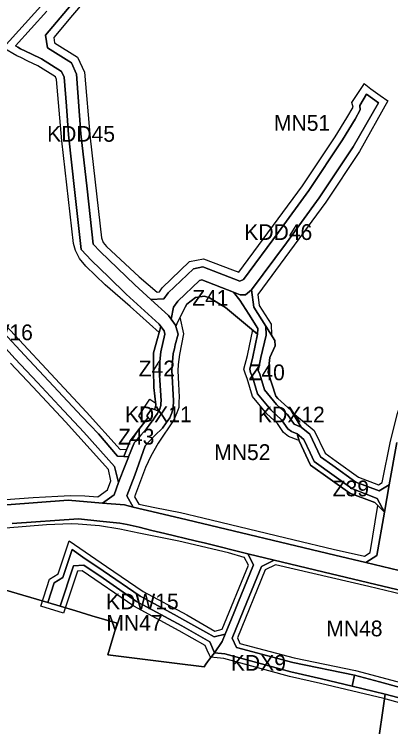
# Model space of a CAD drawing. Extents: x 7428841 to 7433518, y 5545054 to 5546840.
# Drawn here: x 7432461.8 to 7432700.7, y 5545406.8 to 5545858.6 of the extents above; entities that cross this region are included whole.
import ezdxf

# ---------------------------------------------------------------- set-up
doc = ezdxf.new("R2010")
doc.units = 0
for name, color, linetype in [('linie_rozgraniczajace', 7, 'Continuous'), ('linie_zabudowy_nieprzekraczalne', 7, 'Continuous'), ('oznaczenia_przeznaczen', 7, 'Continuous')]:
    doc.layers.add(name, color=color, linetype=linetype)

msp = doc.modelspace()

# ---------------------------------------------------------------- linework, layer by layer
at = {"layer": 'linie_rozgraniczajace'}
for points in [[(7432558.63, 5545936.52), (7432481.55, 5545845.41), (7432482.91, 5545837.42), (7432498.02, 5545827.85), (7432501.36, 5545820.69), (7432504.13, 5545782.79), (7432507.98, 5545747.86), (7432511.82, 5545712.93), (7432516.4, 5545708.16), (7432527.38, 5545697.61), (7432538.36, 5545687.05), (7432548.47, 5545677.77), (7432559.57, 5545667.58), (7432561.31, 5545665.33), (7432564.13, 5545661.41), (7432564.37, 5545660.57), (7432565.72, 5545655.83), (7432563.88, 5545649), (7432563.37, 5545646.48), (7432562.64, 5545643.49), (7432561.84, 5545633.01), (7432562.94, 5545613.42), (7432562.66, 5545609.09), (7432561.75, 5545605.81), (7432560.45, 5545602.74), (7432558.2, 5545599.48), (7432555.94, 5545596.21), (7432550.99, 5545591.47), (7432544.82, 5545584.91), (7432538.38, 5545566.31), (7432533.23, 5545553.18), (7432537.26, 5545546.04), (7432531.75, 5545547.42), (7432517.74, 5545548.62), (7432525.1, 5545553.96), (7432528.01, 5545561.6), (7432530.93, 5545569.23), (7432534.29, 5545577.67), (7432534.38, 5545577.92), (7432537.64, 5545586.11), (7432538.15, 5545587.09), (7432538.76, 5545587.71), (7432542.1, 5545591.65), (7432545.44, 5545595.6), (7432547.39, 5545598), (7432549.14, 5545600.46), (7432549.46, 5545600.9), (7432551.52, 5545603.81), (7432552.57, 5545605.24), (7432553.4, 5545606.61), (7432553.55, 5545606.89), (7432554.01, 5545607.81), (7432554.18, 5545608.45), (7432554.73, 5545610.42), (7432554.82, 5545612.03), (7432554.93, 5545613.48), (7432553.83, 5545633.1), (7432554.4, 5545640.6), (7432554.84, 5545644.48), (7432557.42, 5545655.77), (7432556.82, 5545657.87), (7432554.78, 5545660.7), (7432553.66, 5545662.15), (7432532.88, 5545681.22), (7432521.81, 5545691.86), (7432510.74, 5545702.51), (7432504.17, 5545709.36), (7432500.16, 5545745.7), (7432496.16, 5545782.06), (7432494.83, 5545800.35), (7432493.49, 5545818.64), (7432491.76, 5545822.34), (7432479.05, 5545830.4), (7432472.53, 5545833.46), (7432465.78, 5545836.73), (7432464.01, 5545837.83), (7432462.66, 5545838.66), (7432482.47, 5545860.49)], [(7432704.49, 5545587.01), (7432699.79, 5545560.16), (7432693.37, 5545556.39), (7432678.63, 5545561.96), (7432664.03, 5545572.38), (7432656.21, 5545578.01), (7432649.37, 5545592.44), (7432643.95, 5545596.86), (7432637.44, 5545607.32), (7432629.14, 5545614.87), (7432627.79, 5545616.47), (7432623.02, 5545631.54), (7432623.91, 5545641.02), (7432627.37, 5545648.45), (7432627.24, 5545651.74), (7432621.37, 5545660.86), (7432613.72, 5545672.85), (7432612.39, 5545683.92), (7432634.53, 5545713.76), (7432655.33, 5545742.28), (7432676.79, 5545774.6), (7432693.03, 5545802.53), (7432685.42, 5545807.95), (7432681.02, 5545800.86), (7432681.32, 5545798.03), (7432678.08, 5545792.12), (7432670.04, 5545778.9), (7432648.77, 5545746.86), (7432629.53, 5545720.49), (7432607.23, 5545690.4), (7432604.93, 5545689.4), (7432581.47, 5545698.44), (7432575.45, 5545697.23), (7432559.5, 5545681.95), (7432556.79, 5545678.11), (7432548.47, 5545677.77), (7432538.36, 5545687.05), (7432527.38, 5545697.61), (7432516.4, 5545708.16), (7432511.82, 5545712.93), (7432507.98, 5545747.86), (7432504.13, 5545782.79), (7432501.36, 5545820.69), (7432498.02, 5545827.85), (7432482.91, 5545837.42), (7432481.55, 5545845.41), (7432558.63, 5545936.52)], [(7432482.47, 5545860.49), (7432462.66, 5545838.66), (7432464.01, 5545837.83), (7432465.78, 5545836.73), (7432472.53, 5545833.46), (7432479.05, 5545830.4), (7432491.76, 5545822.34), (7432493.49, 5545818.64), (7432494.83, 5545800.35), (7432496.16, 5545782.06), (7432500.16, 5545745.7), (7432504.17, 5545709.36), (7432510.74, 5545702.51), (7432521.81, 5545691.86), (7432532.88, 5545681.22), (7432553.66, 5545662.15), (7432554.78, 5545660.7), (7432552.65, 5545653.05), (7432550.12, 5545643.98), (7432550.23, 5545632.91), (7432550.34, 5545621.85), (7432551.64, 5545610.97), (7432551.31, 5545609.63), (7432550.74, 5545608.07), (7432549.17, 5545608.7), (7432545.96, 5545604.05), (7432546.83, 5545602.92), (7432542.34, 5545597.27), (7432535.29, 5545588.16), (7432531.26, 5545578.11)], [(7432454.85, 5545656.77), (7432468.21, 5545642.48), (7432486.68, 5545622.85), (7432504.73, 5545603.59), (7432515.22, 5545592.47), (7432527.36, 5545578.35), (7432531.26, 5545578.11), (7432534.38, 5545577.92), (7432534.29, 5545577.67), (7432530.93, 5545569.23), (7432528.01, 5545561.6), (7432525.32, 5545571.85), (7432505.87, 5545593.58), (7432490.18, 5545610.4), (7432476.54, 5545625.02), (7432462.29, 5545640.03), (7432450.07, 5545653.35)], [(7432531.26, 5545578.11), (7432527.36, 5545578.35), (7432515.22, 5545592.47), (7432504.73, 5545603.59), (7432486.68, 5545622.85), (7432468.21, 5545642.48), (7432454.85, 5545656.77)], [(7432450.07, 5545653.35), (7432462.29, 5545640.03), (7432476.54, 5545625.02), (7432490.18, 5545610.4), (7432505.87, 5545593.58), (7432525.32, 5545571.85), (7432528.01, 5545561.6), (7432525.1, 5545553.96), (7432517.74, 5545548.62), (7432495.96, 5545550.47), (7432457.17, 5545547.49)], [(7432706.04, 5545505.84), (7432684.8, 5545510.91), (7432691.96, 5545515.49), (7432696.77, 5545542.91), (7432699.79, 5545560.16), (7432704.49, 5545587.01)], [(7432457.17, 5545547.49), (7432495.96, 5545550.47), (7432517.74, 5545548.62), (7432531.75, 5545547.42), (7432537.26, 5545546.04), (7432552.76, 5545542.38), (7432571.55, 5545537.93), (7432665.2, 5545515.59), (7432684.8, 5545510.91), (7432706.04, 5545505.84)], [(7432460.41, 5545535.59), (7432502.51, 5545538.7), (7432516.17, 5545537.12), (7432528.77, 5545535.81), (7432533.47, 5545535.03), (7432540.95, 5545533.32), (7432549.12, 5545531.31), (7432557.29, 5545529.31), (7432576.6, 5545524.79), (7432583.18, 5545523.21), (7432610.05, 5545516.41), (7432613.65, 5545509.47), (7432603.7, 5545485.19), (7432601.07, 5545478.78), (7432595.66, 5545465.56), (7432588.62, 5545463.74), (7432583.36, 5545466.72), (7432570.05, 5545474.18), (7432563.25, 5545477.9), (7432548.07, 5545486.13), (7432541.74, 5545489.52), (7432518.29, 5545505.58), (7432505.37, 5545514.4), (7432498.47, 5545519.11), (7432492.64, 5545501.43), (7432487.11, 5545498.13), (7432483.05, 5545485.51), (7432456.34, 5545493.47)], [(7432747.03, 5545483.73), (7432662.85, 5545503.81), (7432626.69, 5545512.44), (7432610.05, 5545516.41), (7432583.18, 5545523.21), (7432576.6, 5545524.79), (7432557.29, 5545529.31), (7432549.12, 5545531.31), (7432540.95, 5545533.32), (7432533.47, 5545535.03), (7432528.77, 5545535.81), (7432516.17, 5545537.12), (7432502.51, 5545538.7), (7432460.41, 5545535.59)], [(7432456.34, 5545493.47), (7432483.05, 5545485.51), (7432490.84, 5545483.2), (7432500.9, 5545480.2), (7432510.96, 5545477.21), (7432527.03, 5545472.42), (7432521.06, 5545452.31), (7432563.57, 5545447.17), (7432582.27, 5545444.83), (7432583.41, 5545446.45), (7432584.43, 5545447.9), (7432585.75, 5545449.6), (7432588.89, 5545453.57), (7432595.36, 5545452.95), (7432616.31, 5545447.31), (7432637.26, 5545441.66), (7432656.79, 5545437.08), (7432676.32, 5545432.5), (7432697.15, 5545427.52), (7432691.97, 5545390.71)], [(7432691.97, 5545390.71), (7432697.15, 5545427.52), (7432716.32, 5545422.39), (7432739.46, 5545413.31), (7432747.98, 5545444.14), (7432756.49, 5545474.97), (7432764.84, 5545479.48), (7432780.35, 5545475.78), (7432795.86, 5545472.08), (7432847.64, 5545461.54), (7432848.64, 5545458.32), (7432833.76, 5545435.16), (7432818.19, 5545411.13), (7432812.33, 5545402.01)]]:
    msp.add_lwpolyline(points, dxfattribs=at)
for points in [[(7432548.47, 5545677.77), (7432556.79, 5545678.11), (7432559.5, 5545681.95), (7432575.45, 5545697.23), (7432581.47, 5545698.44), (7432604.93, 5545689.4), (7432607.23, 5545690.4), (7432629.53, 5545720.49), (7432648.77, 5545746.86), (7432670.04, 5545778.9), (7432678.08, 5545792.12), (7432681.32, 5545798.03), (7432681.02, 5545800.86), (7432685.42, 5545807.95), (7432693.03, 5545802.53), (7432676.79, 5545774.6), (7432655.33, 5545742.28), (7432634.53, 5545713.76), (7432612.39, 5545683.92), (7432608.61, 5545680.68), (7432605.11, 5545680.76), (7432601, 5545682.34), (7432580.76, 5545690.14), (7432579.31, 5545689.85), (7432565.61, 5545676.72), (7432562.9, 5545672.94), (7432561.31, 5545665.33), (7432559.57, 5545667.58)], [(7432561.31, 5545665.33), (7432562.9, 5545672.94), (7432565.61, 5545676.72), (7432579.31, 5545689.85), (7432580.76, 5545690.14), (7432601, 5545682.34), (7432604.89, 5545677.39), (7432610.64, 5545668.37), (7432616.4, 5545659.34), (7432616.25, 5545655.79), (7432606.08, 5545664.16), (7432595.85, 5545672.58), (7432585.65, 5545678.8), (7432582.41, 5545679.94), (7432576.7, 5545679), (7432571.34, 5545674.86), (7432570.19, 5545672.88), (7432565.01, 5545662.38), (7432564.37, 5545660.57), (7432564.13, 5545661.41)], [(7432601, 5545682.34), (7432605.11, 5545680.76), (7432608.61, 5545680.68), (7432612.39, 5545683.92), (7432613.72, 5545672.85), (7432621.37, 5545660.86), (7432621.6, 5545655.03), (7432618.17, 5545640.87), (7432616.66, 5545632.77), (7432617.6, 5545630.44), (7432620.68, 5545620.39), (7432628.31, 5545611.19), (7432635.29, 5545604.75), (7432639.46, 5545598.62), (7432643.95, 5545596.86), (7432649.37, 5545592.44), (7432656.21, 5545578.01), (7432664.03, 5545572.38), (7432678.63, 5545561.96), (7432693.37, 5545556.39), (7432699.79, 5545560.16), (7432696.77, 5545542.91), (7432692.18, 5545551.45), (7432676.08, 5545557.93), (7432652.04, 5545575.08), (7432649.54, 5545580.41), (7432645.57, 5545588.88), (7432641.39, 5545592.49), (7432637.64, 5545593.96), (7432635.33, 5545595.81), (7432631.48, 5545601.46), (7432624.67, 5545607.74), (7432620.43, 5545612.85), (7432616.19, 5545617.97), (7432612.88, 5545628.77), (7432611.8, 5545631.44), (7432611.2, 5545633.59), (7432613.13, 5545641.46), (7432616.25, 5545655.79), (7432616.4, 5545659.34), (7432610.64, 5545668.37), (7432604.89, 5545677.39)], [(7432533.23, 5545553.18), (7432538.38, 5545566.31), (7432544.82, 5545584.91), (7432550.99, 5545591.47), (7432555.94, 5545596.21), (7432558.2, 5545599.48), (7432560.45, 5545602.74), (7432561.75, 5545605.81), (7432562.66, 5545609.09), (7432562.94, 5545613.42), (7432561.84, 5545633.01), (7432562.64, 5545643.49), (7432563.37, 5545646.48), (7432563.88, 5545649), (7432565.72, 5545655.83), (7432564.37, 5545660.57), (7432565.01, 5545662.38), (7432570.19, 5545672.88), (7432571.34, 5545674.86), (7432576.7, 5545679), (7432582.41, 5545679.94), (7432585.65, 5545678.8), (7432595.85, 5545672.58), (7432606.08, 5545664.16), (7432616.25, 5545655.79), (7432613.13, 5545641.46), (7432611.2, 5545633.59), (7432611.8, 5545631.44), (7432612.88, 5545628.77), (7432616.19, 5545617.97), (7432620.43, 5545612.85), (7432624.67, 5545607.74), (7432631.48, 5545601.46), (7432635.33, 5545595.81), (7432637.64, 5545593.96), (7432641.39, 5545592.49), (7432642.57, 5545588.03), (7432649.87, 5545572.71), (7432674.82, 5545554.85), (7432690.54, 5545548.91), (7432696.77, 5545542.91), (7432691.96, 5545515.49), (7432684.8, 5545510.91), (7432665.2, 5545515.59), (7432571.55, 5545537.93), (7432552.76, 5545542.38), (7432537.26, 5545546.04)], [(7432550.74, 5545608.07), (7432551.31, 5545609.63), (7432551.64, 5545610.97), (7432550.34, 5545621.85), (7432550.23, 5545632.91), (7432550.12, 5545643.98), (7432552.65, 5545653.05), (7432554.78, 5545660.7), (7432556.82, 5545657.87), (7432557.42, 5545655.77), (7432554.84, 5545644.48), (7432554.4, 5545640.6), (7432553.83, 5545633.1), (7432554.93, 5545613.48), (7432554.82, 5545612.03), (7432554.73, 5545610.42), (7432554.18, 5545608.45), (7432554.01, 5545607.81), (7432553.55, 5545606.89), (7432550.76, 5545608.06)], [(7432616.66, 5545632.77), (7432618.17, 5545640.87), (7432621.6, 5545655.03), (7432621.37, 5545660.86), (7432627.24, 5545651.74), (7432627.37, 5545648.45), (7432623.91, 5545641.02), (7432623.02, 5545631.54), (7432627.79, 5545616.47), (7432629.14, 5545614.87), (7432637.44, 5545607.32), (7432643.95, 5545596.86), (7432639.46, 5545598.62), (7432635.29, 5545604.75), (7432628.31, 5545611.19), (7432620.68, 5545620.39), (7432617.6, 5545630.44)], [(7432545.96, 5545604.05), (7432549.17, 5545608.7), (7432550.74, 5545608.07), (7432550.76, 5545608.06), (7432553.55, 5545606.89), (7432553.4, 5545606.61), (7432552.57, 5545605.24), (7432551.52, 5545603.81), (7432549.46, 5545600.9), (7432549.14, 5545600.46), (7432546.83, 5545602.92)], [(7432531.26, 5545578.11), (7432535.29, 5545588.16), (7432542.34, 5545597.27), (7432546.83, 5545602.92), (7432549.14, 5545600.46), (7432547.39, 5545598), (7432545.44, 5545595.6), (7432542.1, 5545591.65), (7432538.76, 5545587.71), (7432538.15, 5545587.09), (7432537.64, 5545586.11), (7432534.38, 5545577.92)], [(7432641.39, 5545592.49), (7432645.57, 5545588.88), (7432649.54, 5545580.41), (7432652.04, 5545575.08), (7432676.08, 5545557.93), (7432692.18, 5545551.45), (7432696.77, 5545542.91), (7432690.54, 5545548.91), (7432674.82, 5545554.85), (7432649.87, 5545572.71), (7432642.57, 5545588.03)], [(7432483.05, 5545485.51), (7432487.11, 5545498.13), (7432492.64, 5545501.43), (7432498.47, 5545519.11), (7432505.37, 5545514.4), (7432518.29, 5545505.58), (7432541.74, 5545489.52), (7432548.07, 5545486.13), (7432563.25, 5545477.9), (7432570.05, 5545474.18), (7432583.36, 5545466.72), (7432588.62, 5545463.74), (7432595.66, 5545465.56), (7432593.73, 5545460.86), (7432588.89, 5545453.57), (7432585.81, 5545460.72), (7432576.95, 5545465.71), (7432568.09, 5545470.7), (7432546.59, 5545482.37), (7432539.42, 5545486.26), (7432518.13, 5545501.07), (7432505.88, 5545509.21), (7432499.27, 5545508.77), (7432490.84, 5545483.2)], [(7432588.89, 5545453.57), (7432593.73, 5545460.86), (7432595.66, 5545465.56), (7432601.07, 5545478.78), (7432603.7, 5545485.19), (7432613.65, 5545509.47), (7432610.05, 5545516.41), (7432626.69, 5545512.44), (7432618.66, 5545508.52), (7432609.36, 5545485.76), (7432600.07, 5545462.99), (7432602.92, 5545457.15), (7432638.64, 5545447.5), (7432677.64, 5545439.51), (7432676.32, 5545432.5), (7432656.79, 5545437.08), (7432637.26, 5545441.66), (7432616.31, 5545447.31), (7432595.36, 5545452.95)], [(7432490.84, 5545483.2), (7432499.27, 5545508.77), (7432505.88, 5545509.21), (7432518.13, 5545501.07), (7432539.42, 5545486.26), (7432546.59, 5545482.37), (7432568.09, 5545470.7), (7432576.95, 5545465.71), (7432585.81, 5545460.72), (7432588.89, 5545453.57), (7432585.75, 5545449.6), (7432584.43, 5545447.9), (7432583.41, 5545446.45), (7432582.27, 5545444.83), (7432563.57, 5545447.17), (7432521.06, 5545452.31), (7432527.03, 5545472.42), (7432510.96, 5545477.21), (7432500.9, 5545480.2)], [(7432600.07, 5545462.99), (7432609.36, 5545485.76), (7432618.66, 5545508.52), (7432626.69, 5545512.44), (7432662.85, 5545503.81), (7432747.03, 5545483.73), (7432751.3, 5545476.36), (7432750.98, 5545475.2), (7432737.03, 5545425.73), (7432731, 5545422.9), (7432721.44, 5545426.38), (7432706.79, 5545431.71), (7432693.5, 5545435.26), (7432677.64, 5545439.51), (7432638.64, 5545447.5), (7432602.92, 5545457.15)], [(7432676.32, 5545432.5), (7432677.64, 5545439.51), (7432693.5, 5545435.26), (7432706.79, 5545431.71), (7432721.44, 5545426.38), (7432731, 5545422.9), (7432737.03, 5545425.73), (7432750.98, 5545475.2), (7432751.3, 5545476.36), (7432747.03, 5545483.73), (7432764.84, 5545479.48), (7432756.49, 5545474.97), (7432747.98, 5545444.14), (7432739.46, 5545413.31), (7432716.32, 5545422.39), (7432697.15, 5545427.52)]]:
    msp.add_lwpolyline(points, close=True, dxfattribs=at)
at = {"layer": 'linie_zabudowy_nieprzekraczalne'}
for points in [[(7432553.71, 5545656.87), (7432535.29, 5545673.24), (7432519.45, 5545687.14), (7432507.2, 5545698.97), (7432503.13, 5545703.79), (7432500.72, 5545708.71), (7432499.42, 5545713.29), (7432491.95, 5545778.42), (7432488.57, 5545817.36), (7432487.85, 5545818.9), (7432476.64, 5545826.01), (7432470.39, 5545828.94), (7432465.86, 5545831.11), (7432463.4, 5545832.33), (7432454.78, 5545837.43), (7432478.74, 5545863.82), (7432512.66, 5545902.33), (7432533.86, 5545927.37), (7432576.75, 5545979.38), (7432604.6, 5546013.61), (7432608.93, 5546021.42)], [(7432618.1, 5546001.67), (7432562.48, 5545933.32), (7432525.76, 5545889.94), (7432498.81, 5545858.08), (7432486.83, 5545843.91), (7432487.35, 5545840.44), (7432501.92, 5545831.32), (7432506.28, 5545821.97), (7432509.87, 5545780.1), (7432517.13, 5545716.81), (7432518.21, 5545713.86), (7432520.26, 5545711.39), (7432541.01, 5545692.16), (7432552.5, 5545682.35)], [(7432695.36, 5545561.62), (7432700.58, 5545587.88), (7432704.91, 5545605.53), (7432707.27, 5545612.64), (7432721.28, 5545651), (7432735.53, 5545683.2), (7432746.17, 5545705.98), (7432757.15, 5545728.45), (7432775.79, 5545760.35), (7432791.15, 5545790.68), (7432794.62, 5545804.39), (7432795.08, 5545814.24), (7432795.4, 5545826.14), (7432797.74, 5545849.15), (7432799.24, 5545860.38)], [(7432683.89, 5545814.67), (7432687.98, 5545811.34), (7432693.96, 5545807.08), (7432698.83, 5545803.75), (7432680.93, 5545771.53), (7432659.43, 5545739.41), (7432616.28, 5545680.91)], [(7432672.76, 5545792.96), (7432676.96, 5545799.8), (7432676.08, 5545802.71), (7432684.01, 5545814.64)], [(7432552.5, 5545682.35), (7432553.97, 5545682.51), (7432555.69, 5545685.22), (7432573.04, 5545701.85), (7432581.91, 5545703.63), (7432600.21, 5545696.54), (7432604.38, 5545694.97), (7432644.68, 5545749.73), (7432665.35, 5545780.9), (7432672.76, 5545792.96)], [(7432616.28, 5545680.91), (7432617.18, 5545674.02), (7432624.84, 5545662.01), (7432625.09, 5545655.42)], [(7432444.52, 5545673.75), (7432484.92, 5545630.57), (7432507.68, 5545606.3), (7432528.91, 5545582.62), (7432533.15, 5545582.8)], [(7432566.82, 5545666.54), (7432569.21, 5545656.07), (7432566.61, 5545642.85), (7432565.87, 5545636.57), (7432565.58, 5545632.44), (7432565.97, 5545624.16), (7432566.37, 5545615.87), (7432566.3, 5545612.9), (7432566.2, 5545609.3), (7432564.94, 5545605.82), (7432563.04, 5545601.52), (7432553.21, 5545586.6), (7432548.38, 5545578.46), (7432545.07, 5545571.13), (7432538.14, 5545552.62), (7432540.74, 5545548.01)], [(7432641.94, 5545588.52), (7432635.87, 5545590.89), (7432632.73, 5545593.4), (7432628.81, 5545599.16), (7432622.13, 5545605.33), (7432613.05, 5545616.27), (7432609.58, 5545627.59), (7432608.48, 5545630.31), (7432607.57, 5545633.57), (7432609.73, 5545642.25), (7432613.25, 5545658.43)], [(7432523.11, 5545562.82), (7432521.67, 5545569.83), (7432509.92, 5545582.91), (7432494.2, 5545600.12), (7432473.62, 5545622.28), (7432459.36, 5545637.3)], [(7432544.08, 5545599.56), (7432540.91, 5545604.01), (7432547.85, 5545614.48), (7432551.58, 5545612.01)], [(7432638.48, 5545605.85), (7432652.19, 5545594.65), (7432658.99, 5545580.32), (7432666.07, 5545575.22), (7432680.29, 5545565.08), (7432693.04, 5545560.26), (7432695.36, 5545561.62)], [(7432247.77, 5545573.92), (7432259.56, 5545571.46), (7432280.88, 5545567.35), (7432316.46, 5545560.32), (7432327.27, 5545558.29), (7432357.63, 5545553.16), (7432378.33, 5545550.62), (7432387.21, 5545550.01), (7432404.47, 5545548.7), (7432419.02, 5545548.35), (7432424.04, 5545548.71), (7432447.45, 5545550.3), (7432473.79, 5545552.27), (7432489.45, 5545553.01), (7432497.43, 5545553.34), (7432506.55, 5545553.25), (7432514.8, 5545552.66)], [(7432514.8, 5545552.66), (7432520.96, 5545557.14), (7432523.11, 5545562.82)], [(7432540.83, 5545547.97), (7432550.9, 5545545.9), (7432567.2, 5545542.56), (7432581.53, 5545539.29), (7432639.46, 5545525.38), (7432664.09, 5545519.42), (7432684.01, 5545515.04)], [(7432684.01, 5545515.04), (7432687.56, 5545517.33), (7432692.58, 5545547.04)], [(7432607.74, 5545514.22), (7432597.67, 5545516.99), (7432566.17, 5545524.4), (7432540.88, 5545529.57), (7432528.76, 5545532.18), (7432515.92, 5545534.17), (7432502.41, 5545535.32), (7432497.8, 5545535.52), (7432482.16, 5545534.88), (7432456.41, 5545532.76), (7432422.18, 5545530.37), (7432409.49, 5545530.11), (7432393.21, 5545531.14), (7432382.31, 5545531.96), (7432361.79, 5545534.32), (7432340.31, 5545537.64), (7432311.94, 5545542.49), (7432309.79, 5545543.2)], [(7432585.7, 5545452.12), (7432584.25, 5545455.31), (7432583.04, 5545458.27), (7432566.49, 5545467.53), (7432552.08, 5545475.41), (7432537.6, 5545483.27), (7432504.9, 5545505.64), (7432501.86, 5545505.43), (7432493.1, 5545478.88), (7432478.62, 5545483.18), (7432484.18, 5545500.46), (7432489.73, 5545503.76), (7432496.6, 5545524.63), (7432520.27, 5545508.47), (7432543.56, 5545492.52), (7432571.4, 5545477.7), (7432589.13, 5545467.49), (7432593.7, 5545468.67)], [(7432593.68, 5545468.65), (7432610.34, 5545509.31), (7432607.67, 5545514.34)], [(7432627.52, 5545509.5), (7432621.01, 5545506.32), (7432603.35, 5545463.1), (7432605.02, 5545459.69), (7432639.33, 5545450.42), (7432678.33, 5545442.43), (7432707.69, 5545434.57), (7432730.86, 5545426.14), (7432734.51, 5545427.86), (7432748.06, 5545475.97), (7432744.71, 5545481.75)], [(7432744.8, 5545481.71), (7432735.26, 5545483.88), (7432702.59, 5545491.87), (7432686.72, 5545495.72), (7432627.57, 5545509.48), (7432627.57, 5545509.48)], [(7432765.84, 5545476.46), (7432759.48, 5545472.93), (7432741.45, 5545409.31), (7432715.38, 5545419.53), (7432696.42, 5545424.61), (7432656.1, 5545434.16), (7432636.52, 5545438.75), (7432594.82, 5545449.99), (7432586.37, 5545450.84), (7432585.72, 5545452.18)]]:
    msp.add_lwpolyline(points, dxfattribs=at)

# ---------------------------------------------------------------- texts
at = {"layer": 'oznaczenia_przeznaczen'}
for s, p in [('MN51', (7432626.61, 5545784.74)), ('KDD45', (7432482.63, 5545777.79)), ('KDD46', (7432607.79, 5545715.49)), ('Z41', (7432574.7, 5545673.8)), ('KDW16', (7432427.49, 5545651.91)), ('Z42', (7432540.78, 5545628.99)), ('Z40', (7432610.44, 5545626.54)), ('KDX11', (7432532, 5545599.93)), ('KDX12', (7432616.48, 5545599.75)), ('Z43', (7432527.68, 5545585.74)), ('MN52', (7432588.7, 5545575.93)), ('Z39', (7432663.87, 5545552.93)), ('KDW15', (7432520.06, 5545481.26)), ('MN47', (7432520.25, 5545467.66)), ('MN48', (7432659.81, 5545464.14)), ('KDX9', (7432599.26, 5545442.31))]:
    msp.add_text(s, height=10, dxfattribs=at).set_placement(p)

doc.saveas('drawing.dxf')
